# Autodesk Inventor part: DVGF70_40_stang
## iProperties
Created: 2010-04
Part Number: DVGF70_40_stang
Document SubType Name: Modeling
Designer: TB
Mass: 448.187 g
Surface Area: 466.898 cm^2
Volume: 448.187 cm^3
Density: 1 g/cm^3
Author: TB
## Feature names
1. Revolution1
2. Fillet1
3. Revolution2
4. Extrusion1
5. Extrusion2
6. Fillet2
7. Chamfer1
8. Chamfer2
